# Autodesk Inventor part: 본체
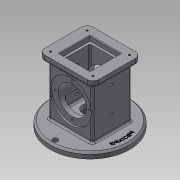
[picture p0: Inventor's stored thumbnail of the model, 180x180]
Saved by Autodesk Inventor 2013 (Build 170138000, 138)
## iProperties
Created: 2019-08
Part Number: 본체
Material: 일반
Document SubType Name: Modeling
Designer: default
Density: 1 g/cm^3
Author: default
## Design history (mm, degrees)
sketch "스케치1"
  geometry: C1 r 67.5 at (0, 0); 1 further point
  constraints: 1 centre point, 1 coincident
  dimensions: "d0" = 135 diameter of C1
extrude "돌출1" new body sketch "스케치1" distance "d2" = 10; taper "d3" = 0 deg
chamfer "모따기1" distance "d4" = 3; stored, may be unused: second distance "d5" = 2, angle "d6" = 45 deg
sketch "스케치2"
  geometry: L1 (-37, 33)-(37, 33); L2 (37, 33)-(37, -33); L3 (37, -33)-(-37, -33); L4 (-37, -33)-(-37, 33); L5 (-37, 33)-(37, -33); L6 (37, 33)-(-37, -33); C1 r 64.5 at (0, 0) reference
  constraints: 12 end point, 2 midpoint, 2 parallel, 1 horizontal, 1 perpendicular
  dimensions: "d7" = 74 distance of L1.start L1.end; "d9" = 66 distance of L1.end L2.end
extrude "돌출2" join sketch "스케치2" distance "d10" = 98; taper "d11" = 0 deg
sketch "스케치3"
  geometry: L1 (37, 33)-(-37, 33) reference; L2 (-37, 33)-(-37, -33) reference; L3 (-37, -33)-(37, -33) reference; L4 (37, -33)-(37, 33) reference; L5 (-46, 41)-(46, 41); L6 (46, 41)-(46, -41); L7 (46, -41)-(-46, -41); L8 (-46, -41)-(-46, 41); L9 (-46, 41)-(46, -41); L10 (46, 41)-(-46, -41); 1 further point
  constraints: 12 end point, 2 midpoint, 2 parallel, 1 horizontal, 1 perpendicular
  dimensions: "d12" = 92 distance of L5.start L5.end; "d14" = 82 distance of L5.end L6.end
extrude "돌출3" join sketch "스케치3" distance "d15" = 10; taper "d16" = 0 deg
fillet "모깎기1" dims "d17" = 10
fillet "모깎기2" dims "d18" = 3
fillet "모깎기3" dims "d19" = 3
fillet "모깎기4" dims "d20" = 3
sketch "스케치4"
  geometry: L1 (34, 36)-(-34, 36) reference; C1 r 64.5 at (0, 0) reference; 2 further points
  constraints: 2 vertical alignment, 1 midpoint
  dimensions: "d21" = 59 distance of C1.centre point (0, 59)
hole "구멍1" sketch "스케치4" at (0, 59) diameter "d22" = 9; stored, may be unused: countersink angle "d26" = 90 deg, drill point angle "d28" = 118 deg; dims "d23" = 6, "d24" = 4, "d25" = 2, "d27" = 8
sketch "스케치5"
  geometry: L1 (-26, 26)-(26, 26); L2 (26, 26)-(26, -26); L3 (26, -26)-(-26, -26); L4 (-26, -26)-(-26, 26); L5 (-26, 26)-(26, -26); L6 (26, 26)-(-26, -26); 1 further point
  constraints: 12 end point, 2 midpoint, 2 parallel, 2 perpendicular, 1 horizontal
  dimensions: "d32" = 52 distance of L1.start L1.end
extrude "돌출4" cut sketch "스케치5" distance "d34" = 8; taper "d35" = 0 deg
sketch "스케치7"
  geometry: L1 (-19, 22)-(19, 22); L2 (22, 19)-(22, -19); L3 (19, -22)-(-19, -22); L4 (-22, -19)-(-22, 19); L5 (-22, 22)-(22, -22); L6 (22, 22)-(-22, -22); A1 r 3 centre (-19, 19) between (-19, 22) and (-22, 19); A2 r 3 centre (19, 19) between (22, 19) and (19, 22); A3 r 3 centre (19, -19) between (19, -22) and (22, -19); A4 r 3 centre (-19, -19) between (-22, -19) and (-19, -22); 1 further point
  constraints: 12 end point, 8 point on circle, 8 point on line, 8 tangent, 4 centre point, 3 equal radius, 2 midpoint, 2 parallel, 2 perpendicular, 1 horizontal
  dimensions: "d36" = 44 distance of L5.start L6.start; "d38" = 3 radius of A1
extrude "돌출5" cut sketch "스케치7" distance "d39" = 74; taper "d40" = 0 deg
sketch "스케치8"
  geometry: L1 (63.5, 0)-(63.5, 10) reference; L2 (63.5, 10)-(64.5, 10) reference; L3 (64.5, 10)-(67.5, 7) reference; L4 (67.5, 7)-(67.5, 0) reference; L5 (67.5, 0)-(63.5, 0) reference; L6 (-37, 13)-(-37, 95) reference; L7 (-40, 98)-(-46, 98) reference; L8 (-46, 98)-(-46, 108) reference; L9 (-46, 108)-(-26, 108) reference; L10 (-26, 108)-(-26, 100) reference; L11 (-26, 100)-(-22, 100) reference; L12 (-22, 100)-(-22, 26) reference; L13 (-22, 26)-(22, 26) reference; L14 (22, 26)-(22, 100) reference; L15 (22, 100)-(26, 100) reference; L16 (26, 100)-(26, 108) reference; L17 (26, 108)-(46, 108) reference; L18 (46, 108)-(46, 98) reference; L19 (46, 98)-(40, 98) reference; L20 (37, 95)-(37, 13) reference; L21 (40, 10)-(54.5, 10) reference; L22 (54.5, 10)-(54.5, 0) reference; L23 (54.5, 0)-(-67.5, 0) reference; L24 (-67.5, 0)-(-67.5, 7) reference; L25 (-67.5, 7)-(-64.5, 10) reference; L26 (-64.5, 10)-(-40, 10) reference; L27 (0, 26)-(0, 0); L28 (-25, 0)-(-25, 18); L29 (-25, 18)-(0, 18); A1 r 3 centre (-40, 13) between (-40, 10) and (-37, 13) reference; A2 r 3 centre (-40, 95) between (-37, 95) and (-40, 98) reference; A3 r 3 centre (40, 95) between (40, 98) and (37, 95) reference; A4 r 3 centre (40, 13) between (37, 13) and (40, 10) reference
  constraints: 6 end point, 2 perpendicular, 2 point on line, 1 midpoint, 1 parallel
  dimensions: "d41" = 50 diameter of L28 L27; "d43" = 18 distance of L28.start L28.end
revolve "회전1" sketch "스케치8" stored, may be unused: angle "d44" = 90 deg
sketch "스케치9"
  geometry: C1 r 25 at (0, 0) reference; C2 r 12.5 at (0, 0)
  constraints: 1 centre point, 1 coincident
  dimensions: "d45" = 25 diameter of C2
extrude "돌출6" cut sketch "스케치9" stored distance "d47" = 74; taper "d48" = 0 deg
sketch "스케치10"
  geometry: A1 r 10 centre (-36, -31) between (-46, -31) and (-36, -41) reference; A2 r 10 centre (36, -31) between (36, -41) and (46, -31) reference; A3 r 10 centre (36, 31) between (46, 31) and (36, 41) reference; A4 r 10 centre (-36, 31) between (-36, 41) and (-46, 31) reference; 1 further point
hole "구멍2" sketch "스케치10" at (-36, 31), (-36, -31), (36, 31), (36, -31) diameter "d49" = 3.242; stored, may be unused: countersink angle "d53" = 90 deg, drill point angle "d55" = 118 deg; dims "d50" = 4, "d51" = 4, "d52" = 2, "d54" = 6
sketch "스케치11"
  geometry: L1 (-33.5, -13)-(101.5, -13) reference; C1 r 35 at (34, 41); 1 further point
  constraints: 1 centre point, 1 vertical alignment
  dimensions: "d56" = 70 diameter of C1; "d58" = 54 distance from line of L1 C1.centre
extrude "돌출7" cut sketch "스케치11" distance "d59" = 3; taper "d60" = 0 deg
sketch "스케치12"
  geometry: C1 r 35 at (0, 0) reference; C2 r 24 at (0, 0); 1 further point
  constraints: 1 centre point, 1 coincident
  dimensions: "d61" = 48 diameter of C2
extrude "돌출8" cut sketch "스케치12" stored distance "d63" = 3; taper "d64" = 0 deg
sketch "스케치13"
  geometry: C1 r 24 at (0, 0) reference; 2 further points
  constraints: 1 vertical alignment
  dimensions: "d65" = 29 distance of C1.centre point (0, 29)
hole "구멍3" sketch "스케치13" at (0, 29) diameter "d66" = 3.242; stored, may be unused: countersink angle "d70" = 90 deg, drill point angle "d72" = 118 deg; dims "d67" = 4, "d68" = 4, "d69" = 2, "d71" = 6
chamfer "모따기2" distance "d76" = 1; stored, may be unused: second distance "d77" = 2, angle "d78" = 45 deg
fillet "모깎기5" dims "d79" = 3
sketch "스케치14"
  geometry: L1 (13, -37.5)-(13, 97.5) reference; 3 further points
  constraints: 2 horizontal alignment
  dimensions: "d80" = 37 distance from line of L1 point (-24, 30); "d81" = 43 distance of point (-24, 30) point (-67, 30)
hole "구멍4" sketch "스케치14" at (-24, 30), (-67, 30) diameter "d82" = 4.917; stored, may be unused: countersink angle "d86" = 90 deg, drill point angle "d88" = 0 deg; dims "d83" = 100, "d84" = 4, "d85" = 2, "d87" = 6
node "작업 평면1"
sketch "스케치15"
  geometry: C1 r 59 at (0, 0); 1 further point
  constraints: 1 centre point, 1 coincident, 1 other
  dimensions: "d90" = 118 diameter of C1
feature "엠보싱1" sketch "스케치15" dims "d92" = 0.5, "d93" = 0
fillet "모깎기6" dims "d94" = 3
fillet "모깎기7" dims "d95" = 3
node "솔리드1"
pattern_circular "원형 패턴1" dims angle "d30" = 180 deg
pattern_circular "원형 패턴2" dims angle "d74" = 360 deg
mirror "대칭1"
node "절단 모서리 투영1"
other parameters: "d89" = 42.75
